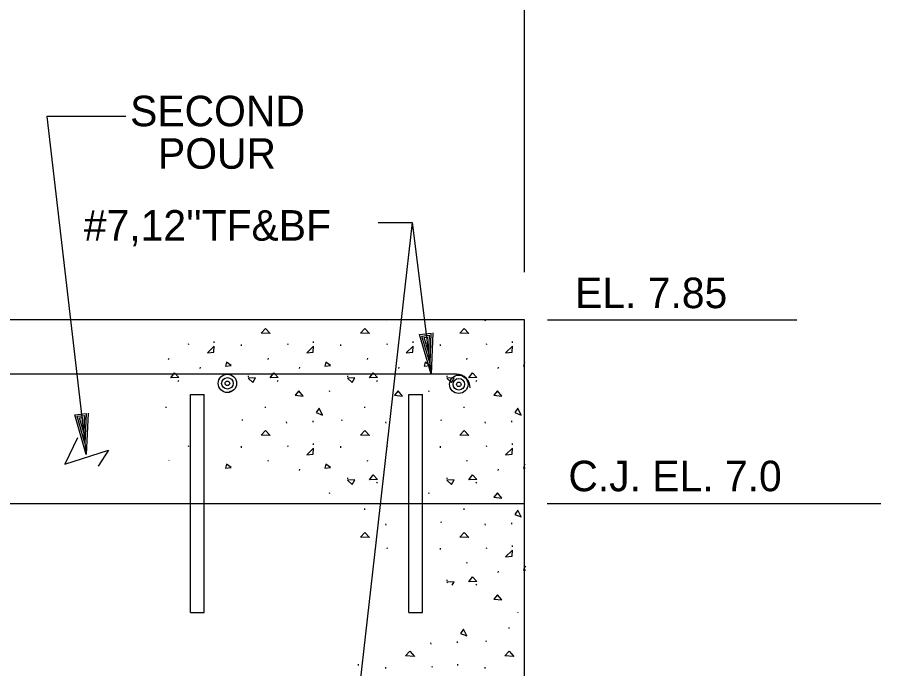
# Model space of a CAD drawing. Extents: x 0 to 320, y -4 to 473.
# Drawn here: x 13.435 to 17.393, y 14.916 to 17.904 of the extents above; entities that cross this region are included whole.
import ezdxf

# ---------------------------------------------------------------- set-up
doc = ezdxf.new("R2010")
doc.units = 0
for name, color, linetype in [('Level 10', 7, 'Continuous'), ('Level 2', 7, 'Continuous'), ('Level 3', 7, 'Continuous'), ('Level 44', 7, 'Continuous'), ('Level 50', 7, 'Continuous')]:
    doc.layers.add(name, color=color, linetype=linetype)

msp = doc.modelspace()

# ---------------------------------------------------------------- linework, layer by layer
at = {"layer": 'Level 10'}
for p, q in [((15.1258, 16.5099), (15.1256, 16.5104)), ((15.5813, 16.5099), (15.5798, 16.5154)), ((15.7026, 16.5149), (15.7026, 16.5167)), ((14.221, 16.4021), (14.2192, 16.4066)), ((14.3382, 16.4112), (14.3382, 16.4171)), ((14.4635, 16.3978), (14.4635, 16.4041)), ((14.6765, 16.4021), (14.6748, 16.4066)), ((14.7937, 16.4112), (14.7937, 16.4171)), ((14.919, 16.3978), (14.919, 16.4041)), ((15.132, 16.4021), (15.1303, 16.4066)), ((15.2492, 16.4112), (15.2492, 16.4171)), ((15.3745, 16.3978), (15.3745, 16.4041)), ((15.5876, 16.4021), (15.5858, 16.4066)), ((15.7048, 16.4112), (15.7048, 16.4171)), ((14.1289, 16.3353), (14.1312, 16.3402)), ((14.5844, 16.3353), (14.5867, 16.3402)), ((15.04, 16.3353), (15.0423, 16.3402)), ((15.4955, 16.3353), (15.4978, 16.3402)), ((14.2735, 16.2933), (14.2744, 16.2994)), ((14.729, 16.2933), (14.73, 16.2994)), ((15.1845, 16.2933), (15.1855, 16.2994)), ((15.6401, 16.2933), (15.641, 16.2994)), ((14.1719, 16.2345), (14.1751, 16.2397)), ((14.4944, 16.2553), (14.4949, 16.2599)), ((14.6275, 16.2345), (14.6306, 16.2397)), ((14.95, 16.2553), (14.9504, 16.2599)), ((15.083, 16.2345), (15.0861, 16.2397)), ((15.4055, 16.2553), (15.4059, 16.2599)), ((15.5385, 16.2345), (15.5416, 16.2397)), ((14.4129, 16.1857), (14.4101, 16.1912)), ((14.8684, 16.1857), (14.8656, 16.1912)), ((15.3239, 16.1857), (15.3211, 16.1912)), ((14.1178, 16.1131), (14.1174, 16.1182)), ((14.5733, 16.1131), (14.5729, 16.1182)), ((15.0288, 16.1131), (15.0284, 16.1182)), ((15.4843, 16.1131), (15.4839, 16.1182)), ((14.4674, 16.0547), (14.4682, 16.0594)), ((14.6703, 16.0423), (14.6685, 16.0485)), ((14.7915, 16.0473), (14.7915, 16.0535)), ((14.9229, 16.0547), (14.9237, 16.0594)), ((15.1258, 16.0423), (15.124, 16.0485)), ((15.3784, 16.0547), (15.3792, 16.0594)), ((15.5813, 16.0423), (15.5795, 16.0485)), ((15.7026, 16.0473), (15.7026, 16.0535)), ((14.221, 15.9345), (14.2192, 15.9389)), ((14.4635, 15.9302), (14.4635, 15.9364)), ((14.6765, 15.9345), (14.6748, 15.9389)), ((14.7937, 15.9436), (14.7937, 15.9495)), ((14.919, 15.9302), (14.919, 15.9364)), ((15.132, 15.9345), (15.1303, 15.9389)), ((15.3745, 15.9302), (15.3745, 15.9364)), ((15.5876, 15.9345), (15.5858, 15.9389)), ((15.7048, 15.9436), (15.7048, 15.9495)), ((14.1305, 15.8711), (14.1312, 15.8726)), ((14.5844, 15.8677), (14.5867, 15.8726)), ((15.04, 15.8677), (15.0423, 15.8726)), ((15.4955, 15.8677), (15.4978, 15.8726)), ((14.729, 15.8257), (14.73, 15.8318)), ((15.6401, 15.8257), (15.641, 15.8318)), ((14.95, 15.7877), (14.9504, 15.7923)), ((15.083, 15.7669), (15.0861, 15.7721)), ((15.4055, 15.7877), (15.4059, 15.7923)), ((15.5385, 15.7669), (15.5416, 15.7721)), ((14.8684, 15.7181), (14.8656, 15.7236)), ((15.3239, 15.7181), (15.3211, 15.7236)), ((15.0288, 15.6455), (15.0284, 15.6506)), ((15.4843, 15.6455), (15.4839, 15.6506)), ((15.1258, 15.5747), (15.124, 15.5809)), ((15.3784, 15.5871), (15.3792, 15.5918)), ((15.5813, 15.5747), (15.5795, 15.5809)), ((15.7026, 15.5797), (15.7026, 15.5859)), ((15.7048, 15.476), (15.7048, 15.4819)), ((15.132, 15.4669), (15.1303, 15.4713)), ((15.3745, 15.4626), (15.3745, 15.4688)), ((15.5876, 15.4669), (15.5858, 15.4713)), ((15.4955, 15.4001), (15.4978, 15.405)), ((15.6401, 15.3581), (15.641, 15.3642)), ((15.4055, 15.3201), (15.4059, 15.3247)), ((15.5385, 15.2993), (15.5416, 15.3045)), ((15.6905, 15.1004), (15.6901, 15.1055)), ((15.5845, 15.042), (15.5854, 15.0466)), ((15.3319, 15.0296), (15.3302, 15.0358)), ((15.4532, 15.0346), (15.4532, 15.0408)), ((14.9998, 14.9309), (14.9998, 14.9368)), ((15.3382, 14.9218), (15.3364, 14.9262)), ((15.4554, 14.9309), (15.4554, 14.9368)), ((15.1252, 14.9175), (15.1252, 14.9237)), ((15.5807, 14.9175), (15.5807, 14.9237))]:
    msp.add_line(p, q, dxfattribs=at)
for points in [[(14.5529, 16.4556), (14.5727, 16.4771), (14.5939, 16.4533)], [(15.0084, 16.4556), (15.0282, 16.4771), (15.0494, 16.4533)], [(15.4639, 16.4556), (15.4837, 16.4771), (15.505, 16.4533)], [(14.3366, 16.3678), (14.3382, 16.3956), (14.3074, 16.3655)], [(14.7921, 16.3678), (14.7937, 16.3956), (14.7629, 16.3655)], [(15.2477, 16.3678), (15.2492, 16.3956), (15.2184, 16.3655)], [(15.7032, 16.3678), (15.7048, 16.3956), (15.6739, 16.3655)], [(14.3894, 16.3043), (14.4148, 16.3075), (14.3935, 16.3218)], [(14.845, 16.3043), (14.8703, 16.3075), (14.849, 16.3218)], [(15.3005, 16.3043), (15.3258, 16.3075), (15.3045, 16.3218)], [(14.1392, 16.2509), (14.156, 16.2731), (14.1749, 16.2518)], [(14.5948, 16.2509), (14.6115, 16.2731), (14.6304, 16.2518)], [(15.0503, 16.2509), (15.067, 16.2731), (15.0859, 16.2518)], [(15.5058, 16.2509), (15.5226, 16.2731), (15.5414, 16.2518)], [(14.4929, 16.2485), (14.5151, 16.2287), (14.5269, 16.2509)], [(14.9484, 16.2485), (14.9706, 16.2287), (14.9825, 16.2509)], [(15.4039, 16.2485), (15.4261, 16.2287), (15.438, 16.2509)], [(14.7456, 16.167), (14.725, 16.1907), (14.7084, 16.171)], [(15.2011, 16.167), (15.1805, 16.1907), (15.1639, 16.171)], [(15.6566, 16.167), (15.636, 16.1907), (15.6194, 16.171)], [(14.8051, 16.091), (14.8335, 16.08), (14.8185, 16.1107)], [(15.7161, 16.091), (15.7445, 16.08), (15.7295, 16.1107)], [(14.5529, 15.988), (14.5727, 16.0095), (14.5939, 15.9857)], [(15.0084, 15.988), (15.0282, 16.0095), (15.0494, 15.9857)], [(15.4639, 15.988), (15.4837, 16.0095), (15.505, 15.9857)], [(14.7921, 15.9002), (14.7937, 15.928), (14.7629, 15.8979)], [(15.7032, 15.9002), (15.7048, 15.928), (15.6739, 15.8979)], [(14.3894, 15.8367), (14.4148, 15.8399), (14.3935, 15.8542)], [(14.845, 15.8367), (14.8703, 15.8399), (14.849, 15.8542)], [(15.0503, 15.7833), (15.067, 15.8055), (15.0859, 15.7842)], [(15.5058, 15.7833), (15.5226, 15.8055), (15.5414, 15.7842)], [(14.9484, 15.7809), (14.9706, 15.7611), (14.9825, 15.7833)], [(15.4039, 15.7809), (15.4261, 15.7611), (15.438, 15.7833)], [(15.6566, 15.6994), (15.636, 15.7231), (15.6194, 15.7034)], [(15.7161, 15.6234), (15.7445, 15.6124), (15.7295, 15.6431)], [(15.0084, 15.5204), (15.0282, 15.5419), (15.0494, 15.5181)], [(15.4639, 15.5204), (15.4837, 15.5419), (15.505, 15.5181)], [(15.7032, 15.4326), (15.7048, 15.4604), (15.6739, 15.4303)], [(15.5058, 15.3157), (15.5226, 15.3379), (15.5414, 15.3166)], [(15.6566, 15.2318), (15.636, 15.2555), (15.6194, 15.2358)], [(15.4667, 15.0783), (15.4952, 15.0673), (15.4802, 15.098)], [(15.2145, 14.9753), (15.2343, 14.9968), (15.2556, 14.973)], [(15.6701, 14.9753), (15.6898, 14.9968), (15.7111, 14.973)]]:
    msp.add_lwpolyline(points, close=True, dxfattribs=at)
for points in [[(15.7618, 16.3206), (15.7601, 16.3218), (15.756, 16.3043)], [(15.756, 16.3043), (15.7618, 16.305)], [(15.764, 15.8515), (15.7601, 15.8542), (15.756, 15.8367)], [(15.756, 15.8367), (15.7641, 15.8377)], [(15.7663, 15.3824), (15.7601, 15.3866), (15.756, 15.3691)], [(15.756, 15.3691), (15.7663, 15.3704)], [(15.4292, 15.2994), (15.438, 15.3157), (15.4039, 15.3133)], [(15.4039, 15.3133), (15.4068, 15.3108)], [(15.7301, 15.1744), (15.7295, 15.1755), (15.7291, 15.1748)]]:
    msp.add_lwpolyline(points, dxfattribs=at)
at = {"layer": 'Level 2'}
for p, q in [((15.7608, 16.5173), (13.2817, 16.5173)), ((15.7608, 13.8403), (15.7608, 16.5173)), ((15.4483, 16.2673), (10.1983, 16.2673)), ((14.2296, 15.1736), (14.2296, 16.1736)), ((14.2921, 15.1736), (14.2921, 16.1736)), ((15.2296, 15.1736), (15.2296, 16.1736)), ((15.2921, 15.1736), (15.2921, 16.1736)), ((9.5414, 15.6736), (15.7608, 15.6736))]:
    msp.add_line(p, q, dxfattribs=at)
at = {"layer": 'Level 3'}
for p, q in [((15.7608, 16.7355), (15.7608, 21.3689)), ((15.8661, 16.5173), (17.0085, 16.5173)), ((15.9304, 16.5173), (16.9657, 16.5173)), ((15.4483, 16.2673), (15.4483, 16.2673)), ((13.7105, 15.9748), (13.6536, 15.8549)), ((13.6536, 15.8549), (13.8527, 15.9194)), ((13.7453, 15.9505), (13.7453, 15.9505)), ((13.8527, 15.9194), (13.8053, 15.8456)), ((13.7513, 15.8989), (13.7513, 15.8989)), ((15.8646, 15.6736), (17.3935, 15.6736))]:
    msp.add_line(p, q, dxfattribs=at)
for points in [[(13.9321, 17.449), (13.5706, 17.449), (13.7513, 15.8989)], [(15.0891, 16.9624), (15.2458, 16.9624), (14.9565, 14.4167)], [(13.7605, 16.0882), (13.7513, 15.8989), (13.6989, 16.081), (13.7515, 16.0872), (13.7453, 15.9505), (13.7098, 16.0743), (13.7435, 16.0782), (13.7395, 16.0002), (13.7206, 16.0675), (13.7345, 16.0691), (13.7335, 16.0518)]]:
    msp.add_lwpolyline(points, dxfattribs=at)
msp.add_arc((15.4483, 16.2048), 0.0625, 0, 90, dxfattribs=at)
at = {"layer": 'Level 44'}
for p, q in [((15.2458, 16.9624), (15.3322, 16.2673)), ((14.2296, 16.1736), (14.2921, 16.1736)), ((15.2296, 16.1736), (15.2921, 16.1736)), ((14.2296, 15.1736), (14.2921, 15.1736)), ((15.2296, 15.1736), (15.2921, 15.1736))]:
    msp.add_line(p, q, dxfattribs=at)
at = {"layer": 'Level 50'}
for p, q in [((15.3257, 16.3189), (15.3257, 16.3189)), ((15.3322, 16.2673), (15.3322, 16.2673))]:
    msp.add_line(p, q, dxfattribs=at)
msp.add_lwpolyline([(15.3399, 16.4567), (15.3322, 16.2673), (15.2783, 16.4491), (15.3309, 16.4556), (15.3257, 16.3189), (15.2892, 16.4424), (15.323, 16.4466), (15.3196, 16.3686), (15.3002, 16.4357), (15.314, 16.4374), (15.3132, 16.4202)], dxfattribs=at)
for centre, radius in [((14.3983, 16.2252), 0.0422), ((14.3983, 16.2252), 0.0264), ((14.3983, 16.2252), 0.0105), ((15.4591, 16.2209), 0.0422), ((15.4591, 16.2209), 0.0264), ((15.4591, 16.2209), 0.0105)]:
    msp.add_circle(centre, radius, dxfattribs=at)

# ---------------------------------------------------------------- texts
at = {"layer": 'Level 3'}
for s, p in [('SECOND', (13.9524, 17.4044)), ('POUR', (14.0801, 17.2095)), ("#7,12''TF&BF", (13.7403, 16.8797)), ('EL. 7.85', (15.9925, 16.5701)), ('C.J. EL. 7.0', (15.9615, 15.7304))]:
    msp.add_text(s, height=0.14, dxfattribs=at).set_placement(p)

doc.saveas('drawing.dxf')
